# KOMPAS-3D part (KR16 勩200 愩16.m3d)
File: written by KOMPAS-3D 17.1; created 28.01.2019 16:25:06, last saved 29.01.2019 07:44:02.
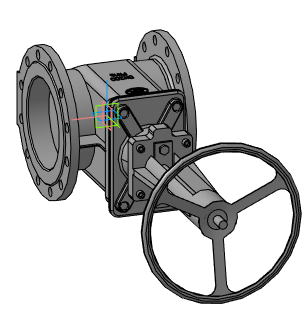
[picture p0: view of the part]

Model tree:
1. Операция без истории:2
